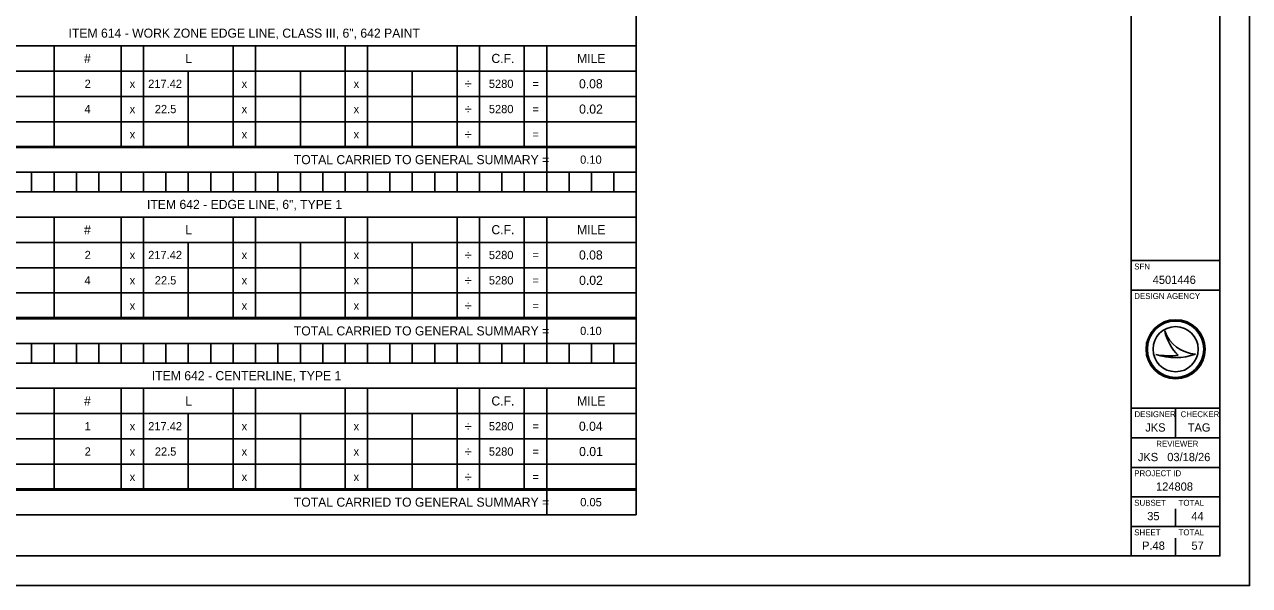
# Model space of a CAD drawing. Extents: x 0 to 34, y 0 to 22.
# Drawn here: x 13.28 to 34, y 0 to 9.5 of the extents above; entities that cross this region are included whole.
import ezdxf

# ---------------------------------------------------------------- set-up
doc = ezdxf.new("R2010")
doc.units = 0
for name, color, linetype in [('SH_Border', 7, 'Continuous'), ('SH_Cut_Line', 7, 'Continuous'), ('SH_Data', 7, 'Continuous'), ('SH_Text', 7, 'Continuous')]:
    doc.layers.add(name, color=color, linetype=linetype)

msp = doc.modelspace()

# ---------------------------------------------------------------- linework, layer by layer
at = {"layer": 'SH_Border'}
for p, q in [((32, 0.5), (32, 21.5)), ((32, 5.5), (33.5, 5.5)), ((32, 5), (33.5, 5)), ((32, 3), (33.5, 3)), ((32.75, 3), (32.75, 2.5)), ((32, 2.5), (33.5, 2.5)), ((32, 2), (33.5, 2)), ((32, 1.5), (33.5, 1.5)), ((32, 1), (33.5, 1))]:
    msp.add_line(p, q, dxfattribs=at)
msp.add_lwpolyline([(1.5, 21.5), (33.5, 21.5), (33.5, 0.5), (1.5, 0.5)], close=True, dxfattribs=at)
at = {"layer": 'SH_Cut_Line'}
msp.add_lwpolyline([(0, 0), (34, 0), (34, 22), (0, 22)], close=True, dxfattribs=at)
at = {"layer": 'SH_Data'}
for p, q in [((32.567, 4.31), (32.567, 4.31)), ((32.75, 4), (32.75, 4)), ((32.417, 3.91), (32.417, 3.91)), ((33.087, 3.919), (33.087, 3.919)), ((32.75, 1), (32.75, 1.3)), ((32.375, 0.675), (32.375, 0.675)), ((32.75, 0.5), (32.75, 0.8))]:
    msp.add_line(p, q, dxfattribs=at)
for radius in [0.5, 0.477, 0.477, 0.382]:
    msp.add_circle((32.75, 4), radius, dxfattribs=at)
for centre, radius, start, end in [((33.116, 4.498), 0.58, 198.9257, 198.9319), ((33.347, 4.47), 0.796, 191.6379, 191.6421), ((33.116, 4.498), 0.58, 198.9319, 267.1657), ((33.347, 4.47), 0.796, 191.6421, 226.0947), ((32.739, 4.87), 1.013, 251.4576, 290.0832), ((32.648, 5.154), 1.266, 259.4964, 259.4995), ((32.739, 4.87), 1.013, 251.4527, 251.4576), ((32.648, 5.154), 1.266, 259.4995, 276.6672)]:
    msp.add_arc(centre, radius, start, end, dxfattribs=at)
at = {"layer": 'SH_Text'}
for p, q in [((23.626, 10.333), (23.626, 7.412)), ((10.367, 9.136), (23.626, 9.136)), ((13.777, 9.136), (13.777, 7.434)), ((14.913, 9.136), (14.913, 7.434)), ((15.292, 9.136), (15.292, 7.434)), ((16.807, 9.136), (16.807, 7.434)), ((17.186, 9.136), (17.186, 7.434)), ((18.701, 9.136), (18.701, 7.434)), ((19.08, 9.136), (19.08, 7.434)), ((20.595, 9.136), (20.595, 7.434)), ((20.974, 9.136), (20.974, 7.434)), ((21.732, 9.136), (21.732, 7.434)), ((22.111, 9.136), (22.111, 7.434)), ((10.367, 8.708), (23.626, 8.708)), ((16.049, 8.708), (16.049, 7.434)), ((17.944, 8.708), (17.944, 7.434)), ((19.838, 8.708), (19.838, 7.434)), ((10.367, 8.279), (23.626, 8.279)), ((10.367, 7.851), (23.626, 7.851)), ((10.367, 7.434), (23.626, 7.434)), ((10.367, 7.412), (23.626, 7.412)), ((22.111, 7.412), (22.111, 6.995)), ((23.626, 7.434), (23.626, 4.513)), ((10.367, 6.995), (23.626, 6.995)), ((10.367, 6.665), (23.626, 6.665)), ((10.367, 6.237), (23.626, 6.237)), ((13.777, 6.237), (13.777, 4.535)), ((14.913, 6.237), (14.913, 4.535)), ((15.292, 6.237), (15.292, 4.535)), ((16.807, 6.237), (16.807, 4.535)), ((17.186, 6.237), (17.186, 4.535)), ((18.701, 6.237), (18.701, 4.535)), ((19.08, 6.237), (19.08, 4.535)), ((20.595, 6.237), (20.595, 4.535)), ((20.974, 6.237), (20.974, 4.535)), ((21.732, 6.237), (21.732, 4.535)), ((22.111, 6.237), (22.111, 4.535)), ((10.367, 5.809), (23.626, 5.809)), ((16.049, 5.809), (16.049, 4.535)), ((17.944, 5.809), (17.944, 4.535)), ((19.838, 5.809), (19.838, 4.535)), ((10.367, 5.38), (23.626, 5.38)), ((10.367, 4.952), (23.626, 4.952)), ((10.367, 4.535), (23.626, 4.535)), ((10.367, 4.513), (23.626, 4.513)), ((22.111, 4.513), (22.111, 4.096)), ((23.626, 4.535), (23.626, 1.614)), ((10.367, 4.096), (23.626, 4.096)), ((10.367, 3.766), (23.626, 3.766)), ((10.367, 3.338), (23.626, 3.338)), ((13.777, 3.338), (13.777, 1.636)), ((14.913, 3.338), (14.913, 1.636)), ((15.292, 3.338), (15.292, 1.636)), ((16.807, 3.338), (16.807, 1.636)), ((17.186, 3.338), (17.186, 1.636)), ((18.701, 3.338), (18.701, 1.636)), ((19.08, 3.338), (19.08, 1.636)), ((20.595, 3.338), (20.595, 1.636)), ((20.974, 3.338), (20.974, 1.636)), ((21.732, 3.338), (21.732, 1.636)), ((22.111, 3.338), (22.111, 1.636)), ((10.367, 2.91), (23.626, 2.91)), ((16.049, 2.91), (16.049, 1.636)), ((17.944, 2.91), (17.944, 1.636)), ((19.838, 2.91), (19.838, 1.636)), ((10.367, 2.482), (23.626, 2.482)), ((10.367, 2.053), (23.626, 2.053)), ((10.367, 1.636), (23.626, 1.636)), ((10.367, 1.614), (23.626, 1.614)), ((22.111, 1.614), (22.111, 1.197)), ((23.626, 1.636), (23.626, 1.197)), ((10.367, 1.197), (23.626, 1.197))]:
    msp.add_line(p, q, dxfattribs=at)
for points in [[(13.019, 6.995), (13.398, 6.995), (13.398, 6.665), (13.019, 6.665)], [(13.398, 6.995), (13.777, 6.995), (13.777, 6.665), (13.398, 6.665)], [(13.777, 6.995), (14.155, 6.995), (14.155, 6.665), (13.777, 6.665)], [(14.155, 6.995), (14.534, 6.995), (14.534, 6.665), (14.155, 6.665)], [(14.534, 6.995), (14.913, 6.995), (14.913, 6.665), (14.534, 6.665)], [(14.913, 6.995), (15.292, 6.995), (15.292, 6.665), (14.913, 6.665)], [(15.292, 6.995), (15.671, 6.995), (15.671, 6.665), (15.292, 6.665)], [(15.671, 6.995), (16.049, 6.995), (16.049, 6.665), (15.671, 6.665)], [(16.049, 6.995), (16.428, 6.995), (16.428, 6.665), (16.049, 6.665)], [(16.428, 6.995), (16.807, 6.995), (16.807, 6.665), (16.428, 6.665)], [(16.807, 6.995), (17.186, 6.995), (17.186, 6.665), (16.807, 6.665)], [(17.186, 6.995), (17.565, 6.995), (17.565, 6.665), (17.186, 6.665)], [(17.565, 6.995), (17.944, 6.995), (17.944, 6.665), (17.565, 6.665)], [(17.944, 6.995), (18.322, 6.995), (18.322, 6.665), (17.944, 6.665)], [(18.322, 6.995), (18.701, 6.995), (18.701, 6.665), (18.322, 6.665)], [(18.701, 6.995), (19.08, 6.995), (19.08, 6.665), (18.701, 6.665)], [(19.08, 6.995), (19.459, 6.995), (19.459, 6.665), (19.08, 6.665)], [(19.459, 6.995), (19.838, 6.995), (19.838, 6.665), (19.459, 6.665)], [(19.838, 6.995), (20.217, 6.995), (20.217, 6.665), (19.838, 6.665)], [(20.217, 6.995), (20.595, 6.995), (20.595, 6.665), (20.217, 6.665)], [(20.595, 6.995), (20.974, 6.995), (20.974, 6.665), (20.595, 6.665)], [(20.974, 6.995), (21.353, 6.995), (21.353, 6.665), (20.974, 6.665)], [(21.353, 6.995), (21.732, 6.995), (21.732, 6.665), (21.353, 6.665)], [(21.732, 6.995), (22.111, 6.995), (22.111, 6.665), (21.732, 6.665)], [(22.111, 6.995), (22.489, 6.995), (22.489, 6.665), (22.111, 6.665)], [(22.489, 6.995), (22.868, 6.995), (22.868, 6.665), (22.489, 6.665)], [(22.868, 6.995), (23.247, 6.995), (23.247, 6.665), (22.868, 6.665)], [(23.247, 6.995), (23.626, 6.995), (23.626, 6.665), (23.247, 6.665)], [(13.019, 4.096), (13.398, 4.096), (13.398, 3.766), (13.019, 3.766)], [(13.398, 4.096), (13.777, 4.096), (13.777, 3.766), (13.398, 3.766)], [(13.777, 4.096), (14.155, 4.096), (14.155, 3.766), (13.777, 3.766)], [(14.155, 4.096), (14.534, 4.096), (14.534, 3.766), (14.155, 3.766)], [(14.534, 4.096), (14.913, 4.096), (14.913, 3.766), (14.534, 3.766)], [(14.913, 4.096), (15.292, 4.096), (15.292, 3.766), (14.913, 3.766)], [(15.292, 4.096), (15.671, 4.096), (15.671, 3.766), (15.292, 3.766)], [(15.671, 4.096), (16.049, 4.096), (16.049, 3.766), (15.671, 3.766)], [(16.049, 4.096), (16.428, 4.096), (16.428, 3.766), (16.049, 3.766)], [(16.428, 4.096), (16.807, 4.096), (16.807, 3.766), (16.428, 3.766)], [(16.807, 4.096), (17.186, 4.096), (17.186, 3.766), (16.807, 3.766)], [(17.186, 4.096), (17.565, 4.096), (17.565, 3.766), (17.186, 3.766)], [(17.565, 4.096), (17.944, 4.096), (17.944, 3.766), (17.565, 3.766)], [(17.944, 4.096), (18.322, 4.096), (18.322, 3.766), (17.944, 3.766)], [(18.322, 4.096), (18.701, 4.096), (18.701, 3.766), (18.322, 3.766)], [(18.701, 4.096), (19.08, 4.096), (19.08, 3.766), (18.701, 3.766)], [(19.08, 4.096), (19.459, 4.096), (19.459, 3.766), (19.08, 3.766)], [(19.459, 4.096), (19.838, 4.096), (19.838, 3.766), (19.459, 3.766)], [(19.838, 4.096), (20.217, 4.096), (20.217, 3.766), (19.838, 3.766)], [(20.217, 4.096), (20.595, 4.096), (20.595, 3.766), (20.217, 3.766)], [(20.595, 4.096), (20.974, 4.096), (20.974, 3.766), (20.595, 3.766)], [(20.974, 4.096), (21.353, 4.096), (21.353, 3.766), (20.974, 3.766)], [(21.353, 4.096), (21.732, 4.096), (21.732, 3.766), (21.353, 3.766)], [(21.732, 4.096), (22.111, 4.096), (22.111, 3.766), (21.732, 3.766)], [(22.111, 4.096), (22.489, 4.096), (22.489, 3.766), (22.111, 3.766)], [(22.489, 4.096), (22.868, 4.096), (22.868, 3.766), (22.489, 3.766)], [(22.868, 4.096), (23.247, 4.096), (23.247, 3.766), (22.868, 3.766)], [(23.247, 4.096), (23.626, 4.096), (23.626, 3.766), (23.247, 3.766)]]:
    msp.add_lwpolyline(points, close=True, dxfattribs=at)

# ---------------------------------------------------------------- texts
at = {"layer": 'SH_Data'}
for s, height, p in [('SFN', 0.1, (32.05, 5.35)), ('4501446', 0.14, (32.363, 5.105)), ('DESIGN AGENCY', 0.1, (32.05, 4.85)), ('DESIGNER', 0.1, (32.054, 2.85)), ('CHECKER', 0.1, (32.835, 2.85)), ('JKS', 0.14, (32.237, 2.605)), ('TAG', 0.14, (32.955, 2.605)), ('REVIEWER', 0.1, (32.422, 2.35)), ('JKS', 0.14, (32.112, 2.105)), ('03/18/26', 0.14, (32.609, 2.105)), ('PROJECT ID', 0.1, (32.05, 1.85)), ('124808', 0.14, (32.419, 1.605)), ('SUBSET', 0.1, (32.05, 1.35)), ('TOTAL', 0.1, (32.8, 1.35)), ('35', 0.14, (32.27, 1.105)), ('44', 0.14, (33.016, 1.105)), ('SHEET', 0.1, (32.05, 0.85)), ('TOTAL', 0.1, (32.8, 0.85)), ('P.48', 0.14, (32.183, 0.605)), ('57', 0.14, (33.018, 0.605))]:
    msp.add_text(s, height=height, dxfattribs=at).set_placement(p)
at = {"layer": 'SH_Text'}
for s, height, p in [('ITEM 614 - WORK ZONE EDGE LINE, CLASS III, 6", 642 PAINT', 0.154, (14.023, 9.273)), ('#', 0.154, (14.286, 8.845)), ('L', 0.154, (15.999, 8.845)), ('C.F.', 0.154, (21.176, 8.845)), ('MILE', 0.154, (22.625, 8.845)), ('2', 0.14, (14.295, 8.423)), ('x', 0.14, (15.057, 8.423)), ('217.42', 0.14, (15.37, 8.423)), ('x', 0.14, (16.951, 8.423)), ('x', 0.14, (18.845, 8.423)), ('÷', 0.168, (20.723, 8.409)), ('5280', 0.14, (21.133, 8.423)), ('=', 0.14, (21.871, 8.423)), ('0.08', 0.154, (22.658, 8.416)), ('4', 0.14, (14.292, 7.995)), ('x', 0.14, (15.057, 7.995)), ('22.5', 0.14, (15.482, 7.995)), ('x', 0.14, (16.951, 7.995)), ('x', 0.14, (18.845, 7.995)), ('÷', 0.168, (20.723, 7.981)), ('5280', 0.14, (21.133, 7.995)), ('=', 0.14, (21.871, 7.995)), ('0.02', 0.154, (22.66, 7.988)), ('x', 0.14, (15.057, 7.567)), ('x', 0.14, (16.951, 7.567)), ('x', 0.14, (18.845, 7.567)), ('÷', 0.168, (20.723, 7.553)), ('=', 0.14, (21.871, 7.567)), ('TOTAL CARRIED TO GENERAL SUMMARY =', 0.154, (17.834, 7.132)), ('0.10', 0.14, (22.677, 7.139)), ('ITEM 642 - EDGE LINE, 6", TYPE 1', 0.154, (15.35, 6.374)), ('#', 0.154, (14.286, 5.946)), ('L', 0.154, (15.999, 5.946)), ('C.F.', 0.154, (21.176, 5.946)), ('MILE', 0.154, (22.625, 5.946)), ('2', 0.14, (14.295, 5.525)), ('x', 0.14, (15.057, 5.525)), ('217.42', 0.14, (15.37, 5.525)), ('x', 0.14, (16.951, 5.525)), ('x', 0.14, (18.845, 5.525)), ('÷', 0.168, (20.723, 5.511)), ('5280', 0.14, (21.133, 5.525)), ('=', 0.14, (21.871, 5.525)), ('0.08', 0.154, (22.658, 5.518)), ('4', 0.14, (14.292, 5.096)), ('x', 0.14, (15.057, 5.096)), ('22.5', 0.14, (15.482, 5.096)), ('x', 0.14, (16.951, 5.096)), ('x', 0.14, (18.845, 5.096)), ('÷', 0.168, (20.723, 5.082)), ('5280', 0.14, (21.133, 5.096)), ('=', 0.14, (21.871, 5.096)), ('0.02', 0.154, (22.66, 5.089)), ('x', 0.14, (15.057, 4.668)), ('x', 0.14, (16.951, 4.668)), ('x', 0.14, (18.845, 4.668)), ('÷', 0.168, (20.723, 4.654)), ('=', 0.14, (21.871, 4.668)), ('TOTAL CARRIED TO GENERAL SUMMARY =', 0.154, (17.834, 4.233)), ('0.10', 0.14, (22.677, 4.24)), ('ITEM 642 - CENTERLINE, TYPE 1', 0.154, (15.432, 3.475)), ('#', 0.154, (14.286, 3.047)), ('L', 0.154, (15.999, 3.047)), ('C.F.', 0.154, (21.176, 3.047)), ('MILE', 0.154, (22.625, 3.047)), ('1', 0.14, (14.295, 2.626)), ('x', 0.14, (15.057, 2.626)), ('217.42', 0.14, (15.37, 2.626)), ('x', 0.14, (16.951, 2.626)), ('x', 0.14, (18.845, 2.626)), ('÷', 0.168, (20.723, 2.612)), ('5280', 0.14, (21.133, 2.626)), ('=', 0.14, (21.871, 2.626)), ('0.04', 0.154, (22.657, 2.619)), ('2', 0.14, (14.295, 2.198)), ('x', 0.14, (15.057, 2.198)), ('22.5', 0.14, (15.482, 2.198)), ('x', 0.14, (16.951, 2.198)), ('x', 0.14, (18.845, 2.198)), ('÷', 0.168, (20.723, 2.184)), ('5280', 0.14, (21.133, 2.198)), ('=', 0.14, (21.871, 2.198)), ('0.01', 0.154, (22.66, 2.191)), ('x', 0.14, (15.057, 1.769)), ('x', 0.14, (16.951, 1.769)), ('x', 0.14, (18.845, 1.769)), ('÷', 0.168, (20.723, 1.755)), ('=', 0.14, (21.871, 1.769)), ('TOTAL CARRIED TO GENERAL SUMMARY =', 0.154, (17.834, 1.334)), ('0.05', 0.14, (22.679, 1.341))]:
    msp.add_text(s, height=height, dxfattribs=at).set_placement(p)

doc.saveas('drawing.dxf')
